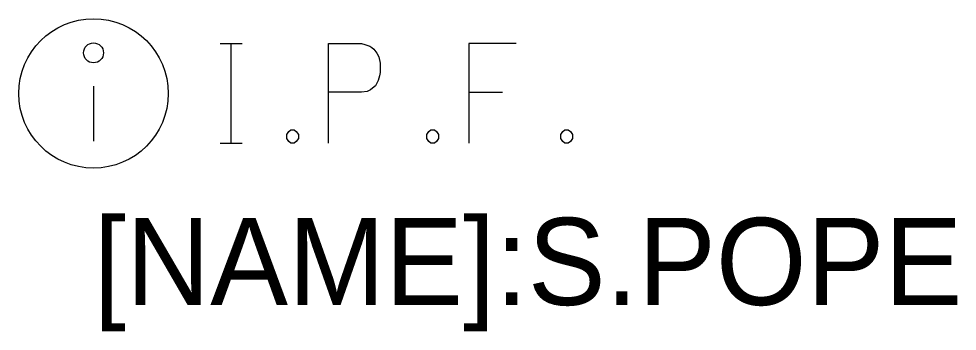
# Model space of a CAD drawing. Extents: x 1386013 to 1389776, y 604170 to 607009.
# Drawn here: x 1386013.39 to 1386028.44, y 604549.07 to 604554.09 of the extents above; entities that cross this region are included whole.
import ezdxf

# ---------------------------------------------------------------- set-up
doc = ezdxf.new("R2010")
doc.units = 0
doc.layers.add('SC_Scratch1', color=7, linetype='Continuous')
doc.layers.add('SV_X_Mon_Cells_Found_Text', color=7, linetype='Continuous')

msp = doc.modelspace()

# ---------------------------------------------------------------- linework, layer by layer
at = {"layer": 'SC_Scratch1'}
msp.add_line((1386014.585, 604553.007), (1386014.585, 604552.123), dxfattribs=at)
for points in [[(1386016.615, 604553.69), (1386016.968, 604553.69)], [(1386016.792, 604552.09), (1386016.792, 604553.69)], [(1386018.357, 604552.09), (1386018.357, 604553.69), (1386018.886, 604553.69), (1386018.941, 604553.677), (1386019.018, 604553.652), (1386019.052, 604553.627), (1386019.084, 604553.602), (1386019.129, 604553.539), (1386019.162, 604553.476), (1386019.184, 604553.375), (1386019.184, 604553.224), (1386019.173, 604553.174), (1386019.151, 604553.098), (1386019.107, 604553.01), (1386019.062, 604552.972), (1386019.029, 604552.947), (1386018.974, 604552.922), (1386018.886, 604552.909), (1386018.357, 604552.909)], [(1386021.366, 604553.69), (1386020.606, 604553.69), (1386020.606, 604552.09)], [(1386020.606, 604552.909), (1386021.146, 604552.909)], [(1386017.751, 604552.304), (1386017.806, 604552.304), (1386017.839, 604552.279), (1386017.872, 604552.229), (1386017.872, 604552.166), (1386017.839, 604552.115), (1386017.806, 604552.09), (1386017.751, 604552.09), (1386017.718, 604552.115), (1386017.685, 604552.166), (1386017.685, 604552.229), (1386017.718, 604552.279), (1386017.751, 604552.304)], [(1386019.999, 604552.304), (1386020.055, 604552.304), (1386020.088, 604552.279), (1386020.121, 604552.229), (1386020.121, 604552.166), (1386020.088, 604552.115), (1386020.055, 604552.09), (1386019.999, 604552.09), (1386019.966, 604552.115), (1386019.933, 604552.166), (1386019.933, 604552.229), (1386019.966, 604552.279), (1386019.999, 604552.304)], [(1386022.149, 604552.304), (1386022.204, 604552.304), (1386022.237, 604552.279), (1386022.27, 604552.229), (1386022.27, 604552.166), (1386022.237, 604552.115), (1386022.204, 604552.09), (1386022.149, 604552.09), (1386022.116, 604552.115), (1386022.083, 604552.166), (1386022.083, 604552.229), (1386022.116, 604552.279), (1386022.149, 604552.304)], [(1386016.615, 604552.09), (1386016.968, 604552.09)]]:
    msp.add_lwpolyline(points, dxfattribs=at)
for centre, radius in [((1386014.585, 604552.89), 1.2), ((1386014.585, 604553.542), 0.16)]:
    msp.add_circle(centre, radius, dxfattribs=at)

# ---------------------------------------------------------------- texts
at = {"layer": 'SV_X_Mon_Cells_Found_Text'}
msp.add_text('[NAME]:S.POPE', height=1.4, dxfattribs=at).set_placement((1386014.585, 604549.49))

doc.saveas('drawing.dxf')
